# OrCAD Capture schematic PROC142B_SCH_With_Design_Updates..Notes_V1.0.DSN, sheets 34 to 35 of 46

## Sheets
34 34. PRU HEADER: size C; title: SOC LFOSC0 AND SOC BOOTMODE INPUT PINS, PRU HEADER
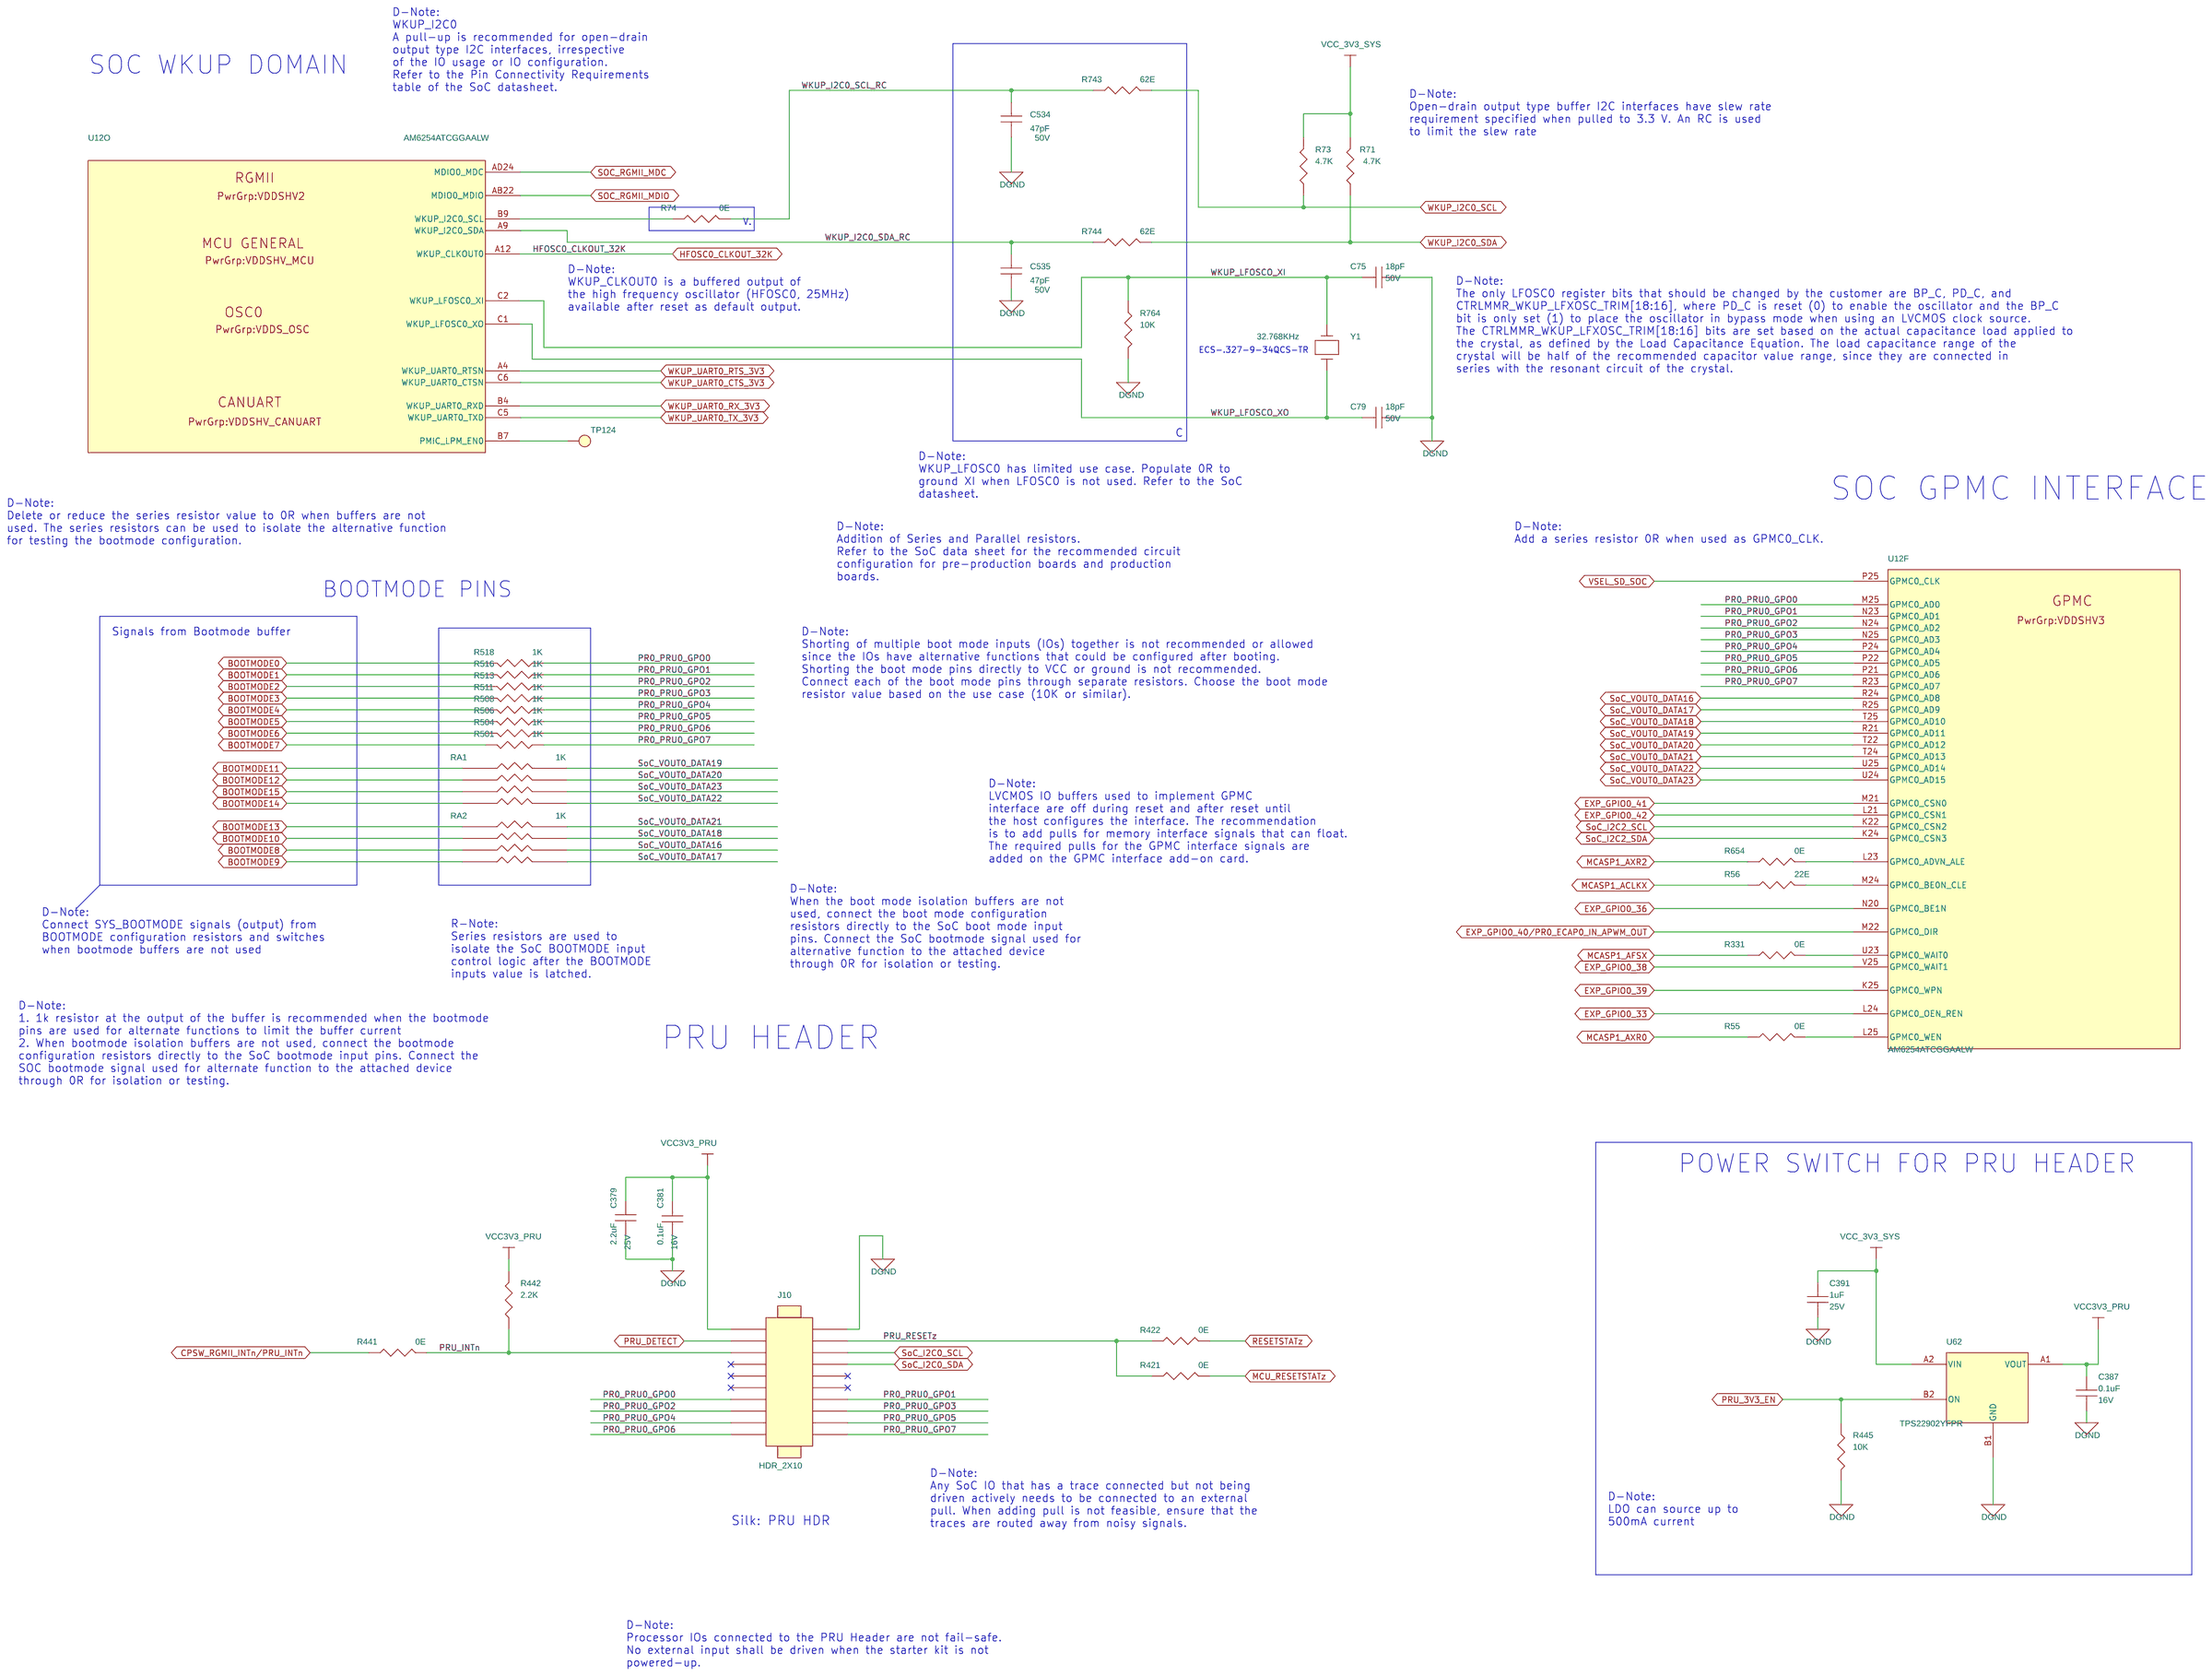
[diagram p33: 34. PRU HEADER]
35 35. USER EXPANSION CONNECTOR: size C; title: USER EXPANSION CONNECTOR
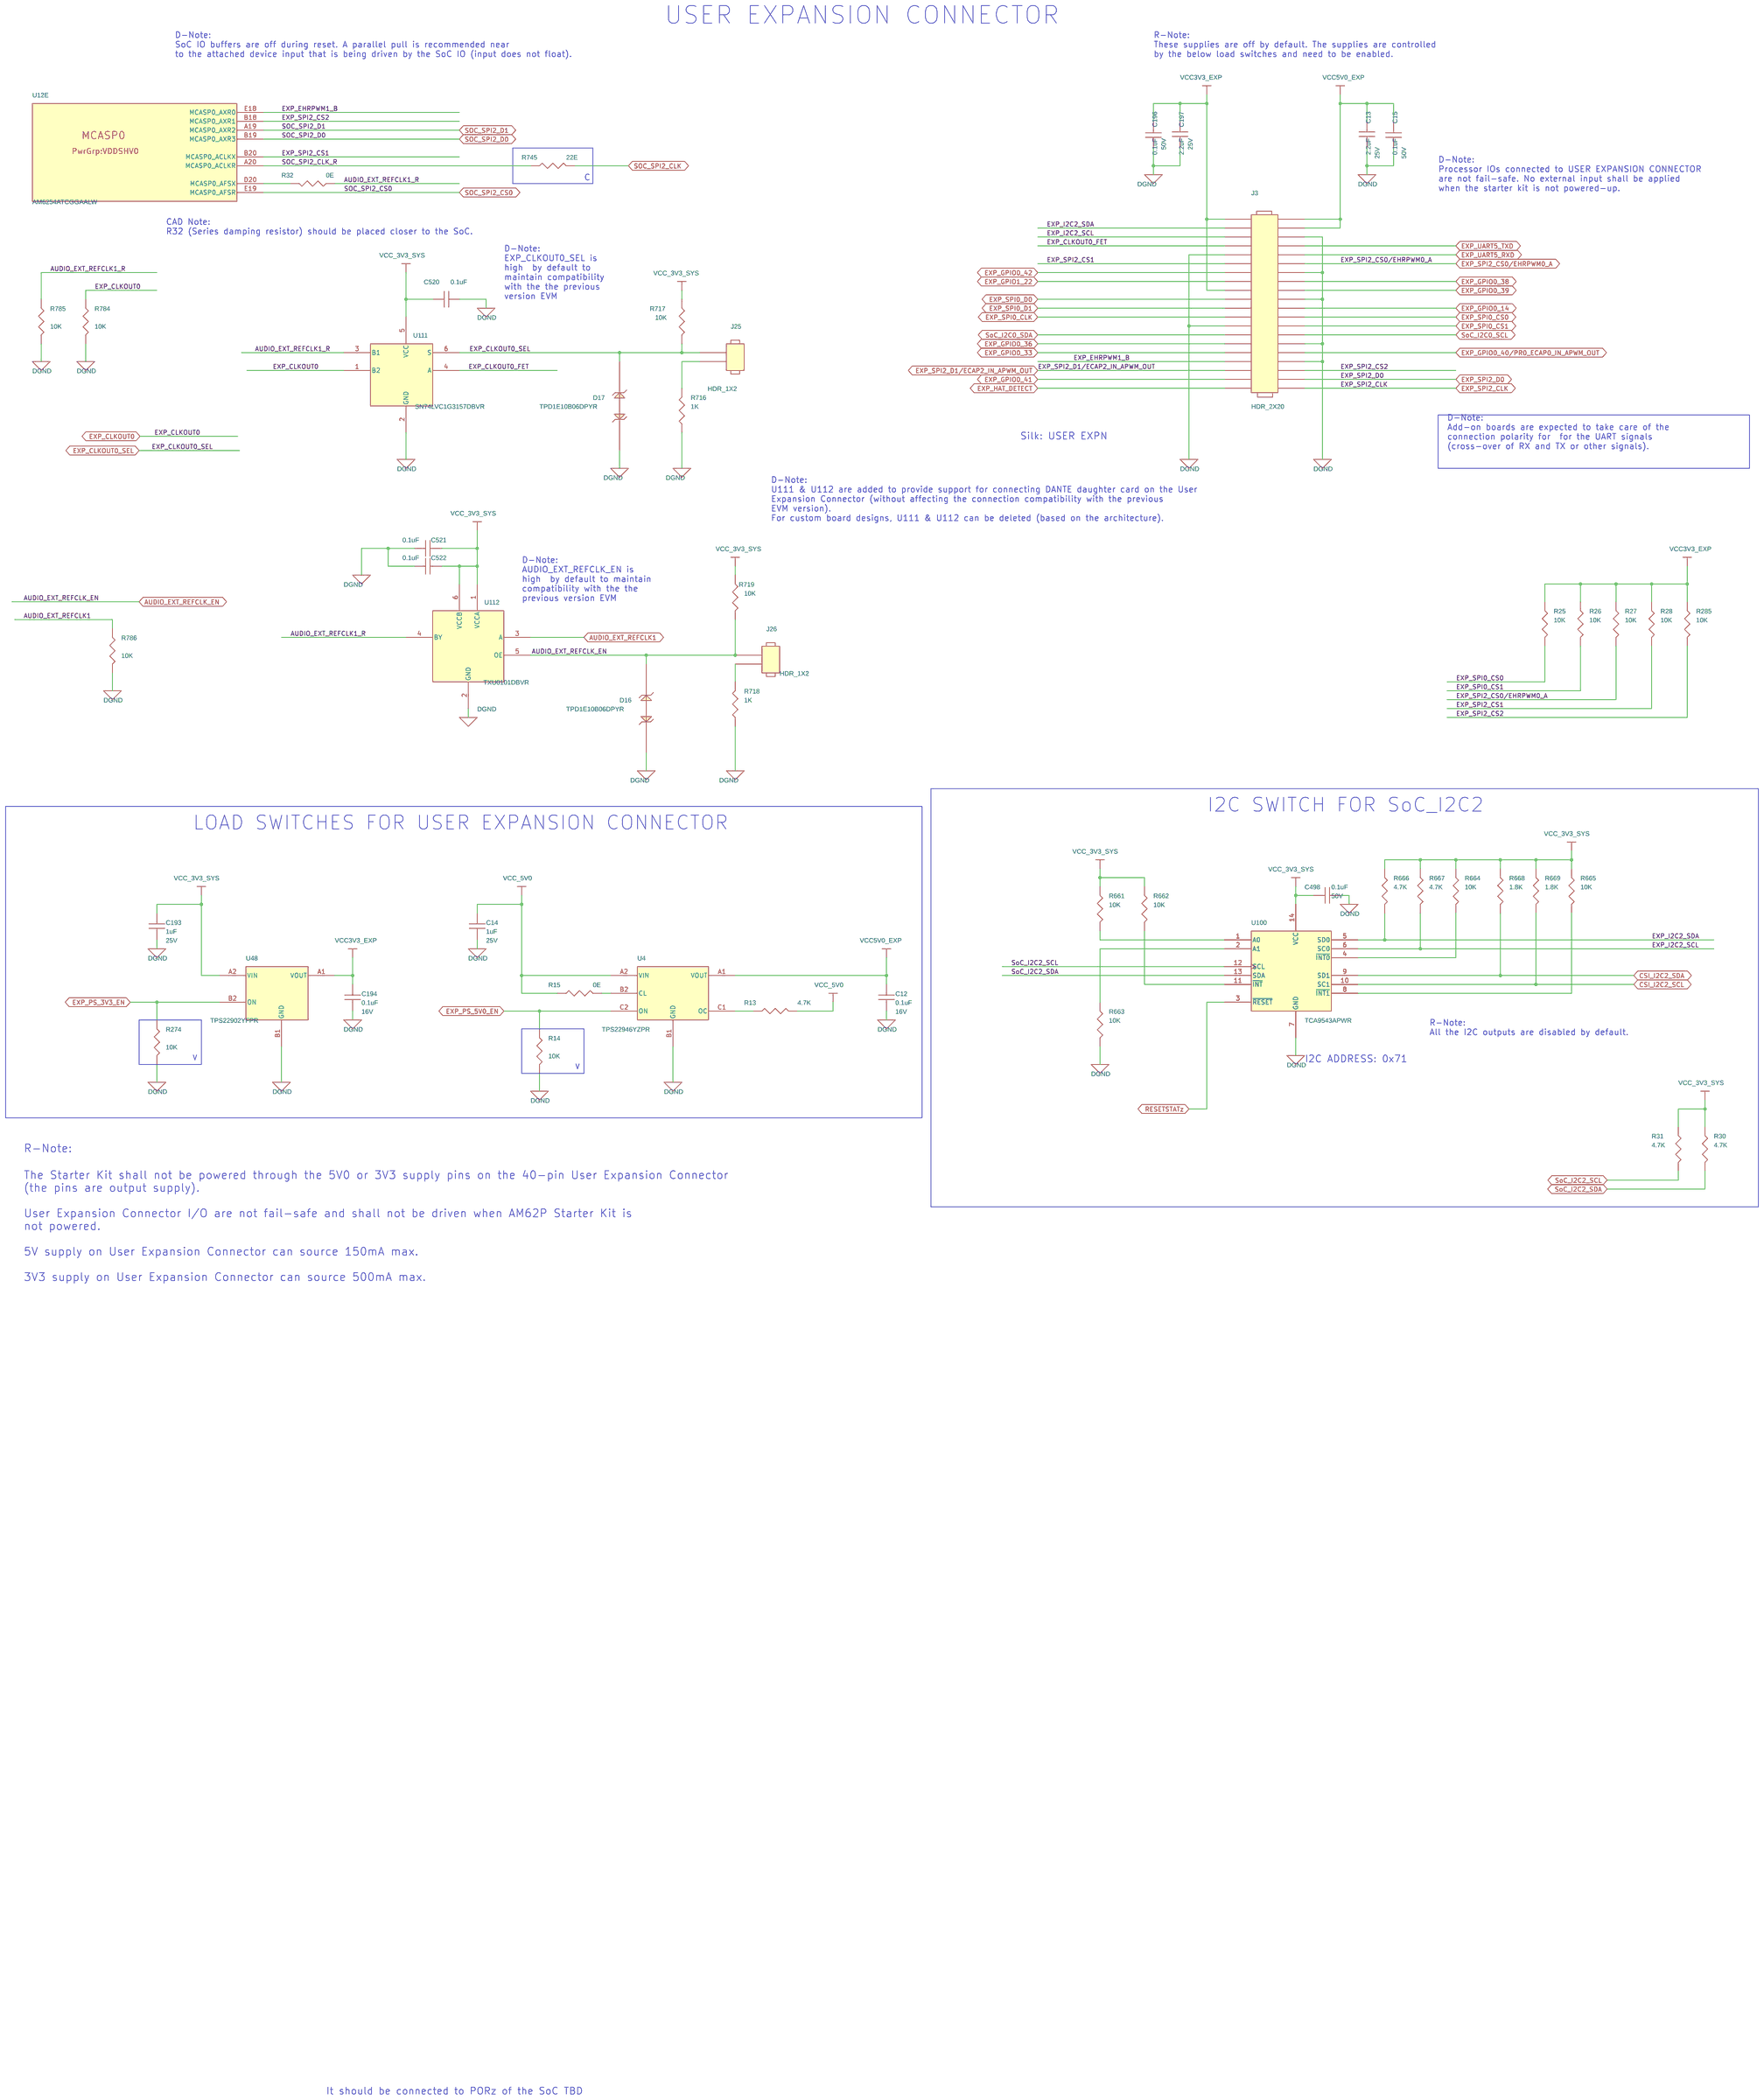
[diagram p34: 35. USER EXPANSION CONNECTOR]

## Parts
sheet 34. PRU HEADER
C75  18pF  [CAP0402_0-75]
C79  18pF  [CAP0402_0-75]
C379  2.2uF  [CAP0402_0-75]
C381  0.1uF  [CAP0201_0-5]
C387  0.1uF  [CAP0201_0-5]
C391  1uF  [CAP0402_0-75]
C534  47pF  [CAP0201_0-5]
C535  47pF  [CAP0201_0-5]
J10  HDR_2X10  [HDR_2X10_PREC010DAAN_S_T_8-4]
R55  0E  [RES0201_0-5]
R56  22E  [RES0402_0-5]
R71  4.7K  [RES0201_0-5]
R73  4.7K  [RES0201_0-5]
R74  0E  [RES0201_0-5]
R331  0E  [RES0201_0-5]
R421  0E  [RES0402_0-5]
R422  0E  [RES0201_0-5]
R441  0E  [RES0201_0-5]
R442  2.2K  [RES0201_0-5]
R445  10K  [RES0402_0-5]
R501  1K  [RES0402_0-5]
R504  1K  [RES0402_0-5]
R506  1K  [RES0402_0-5]
R508  1K  [RES0402_0-5]
R511  1K  [RES0402_0-5]
R513  1K  [RES0402_0-5]
R516  1K  [RES0402_0-5]
R518  1K  [RES0402_0-5]
R654  0E  [RES0201_0-5]
R743  62E  [RES0201_0-5]
R744  62E  [RES0201_0-5]
R764  10K  [RES0402_0-5]
RA1  1K  [RESA_EXB_0201-4_0-5]
RA2  1K  [RESA_EXB_0201-4_0-5]
TP124  TP20_SMD  [TP20_SMD]
U62  TPS22902YFPR  [DSBGA4_15-74_30X30_0-5]
Y1  32.768KHz  [XTAL_ECS-32_130X60_SMD_0-9]
sheet 35. USER EXPANSION CONNECTOR
C12  0.1uF  [CAP0201_0-5]
C13  2.2uF  [CAP0402_0-75]
C14  1uF  [CAP0402_0-75]
C15  0.1uF  [CAP0402_0-75]
C193  1uF  [CAP0402_0-75]
C194  0.1uF  [CAP0201_0-5]
C196  0.1uF  [CAP0402_0-75]
C197  2.2uF  [CAP0402_0-75]
C498  0.1uF  [CAP0402_0-75]
C520  0.1uF  [CAP0402_0-75]
C521  0.1uF  [CAP0201_0-5]
C522  0.1uF  [CAP0201_0-5]
D16  TPD1E10B06DPYR  [DIO_DFN0402_0-5]
D17  TPD1E10B06DPYR  [DIO_DFN0402_0-5]
J3  HDR_2X20  [HDR_2X20_PEC20DAAN_S_T_8-6]
J25  HDR_1X2  [HDR_1X2_90120-0122_S_T_5-6]
J26  HDR_1X2  [HDR_1X2_90120-0122_S_T_5-6]
R13  4.7K  [RES0201_0-5]
R14  10K  [RES0402_0-5]
R15  0E  [RES0201_0-5]
R25  10K  [RES0201_0-5]
R26  10K  [RES0201_0-5]
R27  10K  [RES0201_0-5]
R28  10K  [RES0201_0-5]
R30  4.7K  [RES0201_0-5]
R31  4.7K  [RES0201_0-5]
R32  0E  [RES0201_0-5]
R274  10K  [RES0402_0-5]
R285  10K  [RES0201_0-5]
R661  10K  [RES0201_0-5]
R662  10K  [RES0201_0-5]
R663  10K  [RES0201_0-5]
R664  10K  [RES0201_0-5]
R665  10K  [RES0201_0-5]
R666  4.7K  [RES0201_0-5]
R667  4.7K  [RES0201_0-5]
R668  1.8K  [RES0201_0-5]
R669  1.8K  [RES0201_0-5]
R716  1K  [RES0402_0-5]
R717  10K  [RES0201_0-5]
R718  1K  [RES0402_0-5]
R719  10K  [RES0201_0-5]
R745  22E  [RES0201_0-5]
R784  10K  [RES0402_0-5]
R785  10K  [RES0402_0-5]
R786  10K  [RES0402_0-5]
U4  TPS22946YZPR  [DSBGA6_19-68_40X60_0-5]
U48  TPS22902YFPR  [DSBGA4_15-74_30X30_0-5]
U100  TCA9543APWR  [TSSOP14_25-59_205X180_1-2]
U111  SN74LVC1G3157DBVR  [SOT23-6_1-5]
U112  TXU0101DBVR  [SOT23-6_1-5]
sheet 43. HDMI INTERFACE
U12  AM6254ATCGGAALW  [BGA425_19-68_510X510_0-7]  (sections A,B,C,D,E,F,G,H,I,J,K,L,M,N,O,P,Q,R)

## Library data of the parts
C75 C79 = CAP: CAP CERAMIC 18pF 50V 5% HI-Q C0G(NP0) 0402; Chkd/date: VASANTHA/030315; Crtd /date: NAVEED/271014; Custom_Duty: 15%; Customs_HS_Code: 85322990; Distributor_name: DIGIKEY; Distributor_part_number: 490-3119-1-ND; Footprint Path: Y:\MIS_DATABASE\Library\ALTIUM_TOOL\PCB_FOOTPRINTS\Altium_Footprint_Lib.PcbLib; Height: 0.55MM; Library Path: Y:\MIS_DATABASE\Library\ALTIUM_TOOL\SCHEMATICS_PARTS\MS_DISCRETE_Library.schlib; Mfr_name: MURATA; Mfr_part_number: GJM1555C1H180JB01D; Mistral Part No: 120014100019-R; Package: 0402; Part_type: CAPACITORS\CERAMIC; Project: DC_MIST_RDC; RoHS: RoHS; Temperature: -55°C+125°C; Tolerance: 5%; Voltage: 50V; Wattage: NA; Weight: 6mg; Datasheet: Y:\MIS_DATABASE\DATASHEETS\CAPACITORS\MURATA-GXX-SER_NOV17.PDF
C13 C197 C379 = CAP: CAP CERAMIC 2.2uF 25V 10% X5R 0402; Chkd/date: ALVY/010721; Crtd /date: MANIRAJA/010721; Custom_Duty: 15%; Customs_HS_Code: 85322990; Distributor_name: DIGIKEY; Distributor_part_number: 490-12703-1-ND; Footprint Path: Y:\MIS_DATABASE\Library\ALTIUM_TOOL\PCB_FOOTPRINTS\Altium_Footprint_Lib.PcbLib; Height: 0.70MM; Library Path: Y:\MIS_DATABASE\Library\ALTIUM_TOOL\SCHEMATICS_PARTS\MS_DISCRETE_Library.schlib; Mfr_name: MURATA; Mfr_part_number: GRM155R61E225KE11D; Mistral Part No: 120015120001-R; Package: 0402; Part_type: CAPACITORS\CERAMIC; Project: TI_AM263X_CC; RoHS: RoHS; Temperature: -55°C+85°C; Tolerance: 10%; Voltage: 25V; Wattage: NA; Weight: 1.5mg; Datasheet: Y:\MIS_DATABASE\DATASHEETS\CAPACITORS\GRM155R61E225KE11.PDF
C381 C521 C522 = CAP: CAP CERAMIC 0.1uF 16V 10% X5R 0201; Alt_Mfr_name: YAGEO AMERICA; Alt_Mfr_part_number: CC0402KRX5R8BB104; Chkd/date: MANIRAJA/230118; Crtd /date: MANIRAJA/230118; Custom_Duty: 15%; Customs_HS_Code: 85322990; Distributor_name: DIGIKEY; Distributor_part_number: 490-14305-1-ND; Footprint Path: Y:\MIS_DATABASE\Library\ALTIUM_TOOL\PCB_FOOTPRINTS\Altium_Footprint_Lib.PcbLib; Height: 0.33MM; Library Path: Y:\MIS_DATABASE\Library\ALTIUM_TOOL\SCHEMATICS_PARTS\MS_DISCRETE_Library.schlib; Mfr_name: MURATA; Mfr_part_number: GRM033R61C104KE14D; Mistral Part No: 120009030072-R; Package: 0201; Part_type: CAPACITORS\CERAMIC; Project: TI_MAXIE_CPB; RoHS: RoHS; Temperature: -55°C+85°C; Tolerance: 10%; Voltage: 16V; Wattage: NA; Weight: 0.33mg; Datasheet: Y:\MIS_DATABASE\DATASHEETS\CAPACITORS\GRM033R61C104KE14.PDF
C387 = CAP: CAP CERAMIC 0.1uF 16V 10% X5R 0201; Chkd/date: PRADEEP/130623; Crtd /date: PRADEEP/130623; Custom_Duty: 15%; Customs_HS_Code: 85322990; Distributor_name: NA; Distributor_part_number: NA; Footprint Path: Y:\MIS_DATABASE\Library\ALTIUM_TOOL\PCB_FOOTPRINTS\Altium_Footprint_Lib.PcbLib; Height: 0.33MM; Library Path: Y:\MIS_DATABASE\Library\ALTIUM_TOOL\SCHEMATICS_PARTS\MS_DISCRETE_Library.schlib; Mfr_name: MURATA; Mfr_part_number: GRT033R61C104KE01; Mistral Part No: 120022060019-R; Package: 0201; Part_type: CAPACITORS\CERAMIC; Project: AM62P_SK; RoHS: RoHS; Temperature: -55°C+85°C; Tolerance: 10%; Voltage: 16V; Wattage: NA; Weight: 0.33mg; Datasheet: Y:\MIS_DATABASE\DATASHEETS\CAPACITORS\GRT033R61C104KE01XX.PDF
C14 C193 C391 = CAP: CAP CERAMIC 1uF 25V 10% X6S 0402; Chkd/date: MANIRAJA/140518; Crtd /date: ALVY/140518; Custom_Duty: 15%; Customs_HS_Code: 85322990; Distributor_name: DIGIKEY; Distributor_part_number: 490-10014-1-ND; Footprint Path: Y:\MIS_DATABASE\Library\ALTIUM_TOOL\PCB_FOOTPRINTS\Altium_Footprint_Lib.PcbLib; Height: 0.60MM; Library Path: Y:\MIS_DATABASE\Library\ALTIUM_TOOL\SCHEMATICS_PARTS\MS_DISCRETE_Library.schlib; Mfr_name: MURATA; Mfr_part_number: GRM155C81E105KE11D; Mistral Part No: 120018050004-R; Package: 0402; Part_type: CAPACITORS\CERAMIC; Project: TI_SVB_MAXWELL_DUT; RoHS: RoHS; Temperature: -55°C+105°C; Tolerance: 10%; Voltage: 25V; Wattage: NA; Weight: 6mg; Datasheet: Y:\MIS_DATABASE\DATASHEETS\CAPACITORS\GRM155C81E105KE11X.PDF
C534 C535 = CAP: CAP CERAMIC 47pF 50V 5% C0G(NP0) AUTO 0201; Chkd/date: MANIRAJA/311221; Crtd /date: ALVY/301221; Custom_Duty: 15%; Customs_HS_Code: 85322990; Distributor_name: MOUSER; Distributor_part_number: 81-GRT0335C1H470JA2D; Footprint Path: Y:\MIS_DATABASE\Library\ALTIUM_TOOL\PCB_FOOTPRINTS\Altium_Footprint_Lib.PcbLib; Height: 0.33MM; Library Path: Y:\MIS_DATABASE\Library\ALTIUM_TOOL\SCHEMATICS_PARTS\MS_DISCRETE_Library.schlib; Mfr_name: MURATA; Mfr_part_number: GRT0335C1H470JA02D; Mistral Part No: 120021120018-R; Package: 0201; Part_type: CAPACITORS\CERAMIC; Project: AM62Q_SKEVM_BRD; RoHS: RoHS; Temperature: -55°C+125°C; Tolerance: 5%; Voltage: 50V; Wattage: NA; Weight: 0.33mg; Datasheet: Y:\MIS_DATABASE\DATASHEETS\CAPACITORS\GRT0335C1H470JA02.PDF
J10 = HEADER_10X2: CON HDR 2X10 2.54MM PITCH ST TH; Chkd/date: MANIRAJA/270721; Crtd /date: ALVY/260721; Custom_Duty: 24%; Customs_HS_Code: 85369090; Distributor_name: DIGIKEY; Distributor_part_number: S2012EC-10-ND; Footprint Path: Y:\MIS_DATABASE\Library\ALTIUM_TOOL\PCB_FOOTPRINTS\Altium_Footprint_Lib.PcbLib; Height: 8.34MM; Library Path: Y:\MIS_DATABASE\Library\ALTIUM_TOOL\SCHEMATICS_PARTS\MS_CONNECTOR_Library.schlib; Mfr_name: SULLINS CONNECTOR; Mfr_part_number: PREC010DAAN-RC; Mistral Part No: 150021070022-R; Package: THRU-HOLE; Part_type: CONNECTOR\HEADERS; Project: TI_AM335x SK_BRD; RoHS: RoHS; Temperature: -40°C+105°C; Tolerance: NA; Voltage: NA; Wattage: NA; Weight: NA; Datasheet: Y:\MIS_DATABASE\DATASHEETS\CONNECTORS\PRPCXXDXXN-SER.PDF
R55 R74 R331 R654 = RESISTOR: RES 0E 1/20W 5% 0201; Chkd/date: NAVEED/301214; Crtd /date: MUDDU/120710; Custom_Duty: 15%; Customs_HS_Code: 85332119; Distributor_name: DIGIKEY; Distributor_part_number: 311-0.0NCT-ND; Footprint Path: Y:\MIS_DATABASE\Library\ALTIUM_TOOL\PCB_FOOTPRINTS\Altium_Footprint_Lib.PcbLib; Height: 0.26MM; Library Path: Y:\MIS_DATABASE\Library\ALTIUM_TOOL\SCHEMATICS_PARTS\MS_DISCRETE_Library.schlib; Mfr_name: YAGEO AMERICA; Mfr_part_number: RC0201JR-070RL; Mistral Part No: 110010070067-R; Package: 0201; Part_type: RESISTORS\FIXED; Project: PB_BUGBASE; RoHS: RoHS; SIGNAL_MODEL: RESISTOR_RES0201_0-5_0E_0E; Temperature: -55°C+125°C; Tolerance: 5%; Voltage: NA; Wattage: 1/20W; Weight: 0.17mg; Datasheet: Y:\MIS_DATABASE\DATASHEETS\RESISTORS\RCXXXXL-SER_MAR18.PDF
R56 = RESISTOR: RES 22E 1/16W 5% 0402; Chkd/date: ALVY/210122; Crtd /date: TAMILARASU/210122; Custom_Duty: 15%; Customs_HS_Code: 85332119; Distributor_name: DIGIKEY; Distributor_part_number: 311-22JRCT-ND; Footprint Path: Y:\MIS_DATABASE\Library\ALTIUM_TOOL\PCB_FOOTPRINTS\Altium_Footprint_Lib.PcbLib; Height: 0.40MM; Library Path: Y:\MIS_DATABASE\Library\ALTIUM_TOOL\SCHEMATICS_PARTS\MS_DISCRETE_Library.schlib; Manufacturer: YAGEO; Mfr_name: YAGEO AMERICA; Mfr_part_number: RC0402JR-0722RL; Mistral Part No: 110022010018-R; Package: 0402; Part_type: RESISTORS\FIXED; Project: DLRL DIGITAL RECEIVER_BRD; RoHS: RoHS; Temperature: -55°C+155°C; Tolerance: 5%; Voltage: NA; Wattage: 1/16W; Weight: 0.65mg; Datasheet: Y:\MIS_DATABASE\DATASHEETS\RESISTORS\RCXXXXP-SER_SEP18.PDF
R13 R30 R31 R71 R73 R666 R667 = RESISTOR: RES 4.7K 1/20W 5% 0201; Chkd/date: MANIRAJA/200921; Crtd /date: ALVY/200921; Custom_Duty: 15%; Customs_HS_Code: 85332119; Distributor_name: DIGIKEY; Distributor_part_number: 311-4.7KNCT-ND; Footprint Path: Y:\MIS_DATABASE\Library\ALTIUM_TOOL\PCB_FOOTPRINTS\Altium_Footprint_Lib.PcbLib; Height: 0.26MM; Library Path: Y:\MIS_DATABASE\Library\ALTIUM_TOOL\SCHEMATICS_PARTS\MS_DISCRETE_Library.schlib; Mfr_name: YAGEO AMERICA; Mfr_part_number: RC0201JR-074K7L; Mistral Part No: 110021090007-R; Package: 0201; Part_type: RESISTORS\FIXED; Project: TI_AM62x SKEVM_BRD; RoHS: RoHS; Temperature: -55°C+125°C; Tolerance: 5%; Voltage: NA; Wattage: 1/20W; Weight: 0.17mg; Datasheet: Y:\MIS_DATABASE\DATASHEETS\RESISTORS\RCXXXXL-SER_MAR18.PDF
R421 = RESISTOR: RES 0E 1/16W JUMPER 0402; Chkd/date: VASANTHA/201216; Crtd /date: MUDDU/190810; Custom_Duty: 15%; Customs_HS_Code: 85332119; Distributor_name: DIGIKEY; Distributor_part_number: 541-0.0JCT-ND; Footprint Path: Y:\MIS_DATABASE\Library\ALTIUM_TOOL\PCB_FOOTPRINTS\Altium_Footprint_Lib.PcbLib; Height: 0.40MM; Library Path: Y:\MIS_DATABASE\Library\ALTIUM_TOOL\SCHEMATICS_PARTS\MS_DISCRETE_Library.schlib; Mfr_name: VISHAY; Mfr_part_number: CRCW04020000Z0ED; Mistral Part No: 110010080019-R; Package: 0402; Part_type: RESISTORS\FIXED; Project: PB_BUGBASE; RoHS: RoHS; Temperature: -55°C+155°C; Tolerance: NA; Voltage: NA; Wattage: 1/16W; Weight: 0.65mg; Datasheet: Y:\MIS_DATABASE\DATASHEETS\RESISTORS\CRCW0603.PDF
R15 R32 R422 R441 = RESISTOR: RES 0E 1/20W 5% 0201; Chkd/date: NAVEED/301214; Crtd /date: MUDDU/120710; Custom_Duty: 15%; Customs_HS_Code: 85332119; Distributor_name: DIGIKEY; Distributor_part_number: 311-0.0NCT-ND; Footprint Path: Y:\MIS_DATABASE\Library\ALTIUM_TOOL\PCB_FOOTPRINTS\Altium_Footprint_Lib.PcbLib; Height: 0.26MM; Library Path: Y:\MIS_DATABASE\Library\ALTIUM_TOOL\SCHEMATICS_PARTS\MS_DISCRETE_Library.schlib; Mfr_name: YAGEO AMERICA; Mfr_part_number: RC0201JR-070RL; Mistral Part No: 110010070067-R; Package: 0201; Part_type: RESISTORS\FIXED; Project: PB_BUGBASE; RoHS: RoHS; Temperature: -55°C+125°C; Tolerance: 5%; Voltage: NA; Wattage: 1/20W; Weight: 0.17mg; Datasheet: Y:\MIS_DATABASE\DATASHEETS\RESISTORS\RCXXXXL-SER_MAR18.PDF
R442 = RESISTOR: RES 2.2K 1/20W 5% 0201; Chkd/date: VASANTHA/010117; Crtd /date: MAZHAR/010605; Custom_Duty: 15%; Customs_HS_Code: 85332119; Distributor_name: DIGIKEY; Distributor_part_number: P2.2KAGCT-ND; Footprint Path: Y:\MIS_DATABASE\Library\ALTIUM_TOOL\PCB_FOOTPRINTS\Altium_Footprint_Lib.PcbLib; Height: 0.26MM; Library Path: Y:\MIS_DATABASE\Library\ALTIUM_TOOL\SCHEMATICS_PARTS\MS_DISCRETE_Library.schlib; Mfr_name: PANASONIC-ECG; Mfr_part_number: ERJ-1GEJ222C; Mistral Part No: 110009030427-R; Package: 0201; Part_type: RESISTORS\FIXED; Project: G4SLIM; RoHS: RoHS; Temperature: -55°C+125°C; Tolerance: 5%; Voltage: NA; Wattage: 1/20W; Weight: 0.15mg; Datasheet: Y:\MIS_DATABASE\DATASHEETS\RESISTORS\PAN-ERJXGE-FEB06.PDF
R14 R274 R445 R764 R784-R786 = RESISTOR: RES 10K 1/16W 5% 0402; Chkd/date: MANIRAJA/120219; Crtd /date: MANIRAJA/120219; Custom_Duty: 15%; Customs_HS_Code: 85332119; Distributor_name: DIGIKEY; Distributor_part_number: 541-10KJCT-ND; Footprint Path: Y:\MIS_DATABASE\Library\ALTIUM_TOOL\PCB_FOOTPRINTS\Altium_Footprint_Lib.PcbLib; Height: 0.40MM; Library Path: Y:\MIS_DATABASE\Library\ALTIUM_TOOL\SCHEMATICS_PARTS\MS_DISCRETE_Library.schlib; Mfr_name: VISHAY; Mfr_part_number: CRCW040210K0JNED; Mistral Part No: 110011060021-R; Package: 0402; Part_type: RESISTORS\FIXED; Project: NEXTNAV_ORBIT_MODULE; RoHS: RoHS; Temperature: -55°C+155°C; Tolerance: 5%; Voltage: NA; Wattage: 1/16W; Weight: 0.65mg; Datasheet: Y:\MIS_DATABASE\DATASHEETS\RESISTORS\CRCW0603.PDF
R501 R504 R506 R508 R511 R513 R516 R518 R716 R718 = RESISTOR: RES 1K 1/10W 5% 0402; Chkd/date: VASANTHA/201216; Crtd /date: MAZHAR/230805; Custom_Duty: 15%; Customs_HS_Code: 85332119; Distributor_name: DIGIKEY; Distributor_part_number: P1.0KJCT-ND; Footprint Path: Y:\MIS_DATABASE\Library\ALTIUM_TOOL\PCB_FOOTPRINTS\Altium_Footprint_Lib.PcbLib; Height: 0.40MM; Library Path: Y:\MIS_DATABASE\Library\ALTIUM_TOOL\SCHEMATICS_PARTS\MS_DISCRETE_Library.schlib; Mfr_name: PANASONIC-ECG; Mfr_part_number: ERJ-2GEJ102X; Mistral Part No: 110009030400-R; Package: 0402; Part_type: RESISTORS\FIXED; Project: HSE; RoHS: RoHS; Temperature: -55°C+155°C; Tolerance: 5%; Voltage: NA; Wattage: 1/10W; Weight: 0.8mg; Datasheet: Y:\MIS_DATABASE\DATASHEETS\RESISTORS\PAN-ERJSER_NOV17.PDF
R743 R744 = RESISTOR: RES 62E 1/20W 1% 0201; Chkd/date: PRADEEP/230326; Crtd /date: SHANKARI/230326; Custom_Duty: 15%; Customs_HS_Code: 85332119; Distributor_name: DIGIKEY; Distributor_part_number: P123108CT-ND; Footprint Path: Y:\MIS_DATABASE\Library\ALTIUM_TOOL\PCB_FOOTPRINTS\Altium_Footprint_Lib.PcbLib; Height: 0.26MM; Library Path: Y:\MIS_DATABASE\Library\ALTIUM_TOOL\SCHEMATICS_PARTS\MS_DISCRETE_Library.schlib; Mfr_name: PANASONIC; Mfr_part_number: ERJ-1GNF62R0C; Mistral Part No: 110026030006-R; Package: 0201; Part_type: RESISTORS\FIXED; Project: AM62X_FULTON_REV B; RoHS: RoHS; Temperature: -55°C+125°C; Tolerance: 0.01; Voltage: NA; Wattage: 1/20W; Weight: NA; Datasheet: Y:\MIS_DATABASE\DATASHEETS\RESISTORS\ERJ-1GNF62R0C.PDF
RA1 RA2 = RESARR_ISO4: RES ARRAY 1K 31mW 5% 0201-4; Chkd/date: NAVEED/110515; Crtd /date: VASANTHA/080515; Custom_Duty: 15%; Customs_HS_Code: 85332119; Distributor_name: DIGIKEY; Distributor_part_number: Y6102CT-ND; Footprint Path: Y:\MIS_DATABASE\Library\ALTIUM_TOOL\PCB_FOOTPRINTS\Altium_Footprint_Lib.PcbLib; Height: 0.45MM; Library Path: Y:\MIS_DATABASE\Library\ALTIUM_TOOL\SCHEMATICS_PARTS\MS_DISCRETE_Library.schlib; Manufacturer: PANASONIC-ECG; Mfr_part_number: EXB-18V102JX; Mistral Part No: 110015050003-R; Package: 0201-4; Part_type: RESISTORS\ARRAY; Project: FREE SCALE NANO; RoHS: RoHS; Temperature: -55°C+125°C; Tolerance: 5%; Voltage: NA; Wattage: 31mW; Weight: 1mg; Datasheet: Y:\MIS_DATABASE\DATASHEETS\RESISTORS\EXB-18V.PDF
TP124 = TESTPOINT: TESTPOINT CIR 20 SMD; Chkd/date: SHREESHAIL/171006; Crtd /date: MAZHAR/171006; Custom_Duty: NA; Customs_HS_Code: NA; Distributor_name: NA; Distributor_part_number: NA; Footprint Path: Y:\MIS_DATABASE\Library\ALTIUM_TOOL\PCB_FOOTPRINTS\Altium_Footprint_Lib.PcbLib; Height: NA; Library Path: Y:\MIS_DATABASE\Library\ALTIUM_TOOL\SCHEMATICS_PARTS\MS_DISCRETE_Library.schlib; MECHANICAL 3D STEP FILE: NA; Mfr_name: LOCAL; Mistral Part No: NA; Package: SMD; Project: BT MODULE_CSRBC04; RoHS: NA; Temperature: NA; Tolerance: NA; Voltage: NA; Wattage: NA; Weight: NA; Datasheet: NA
U48 U62 = TPS22912CYZVR_DSBGA4: IC 3.6V 500mA 78mE ON-RESISTANCE LOAD SWITCH WITH CONTROLLED TURNON DSBGA4; Chkd/date: MANIRAJA/170920; Crtd /date: ALVY/160920; Custom_Duty: 15%; Customs_HS_Code: 85423100; Distributor_name: DIGIKEY; Distributor_part_number: 296-24472-1-ND; Footprint Path: Y:\MIS_DATABASE\Library\ALTIUM_TOOL\PCB_FOOTPRINTS\Altium_Footprint_Lib.PcbLib; Height: 0.50MM; Library Path: Y:\MIS_DATABASE\Library\ALTIUM_TOOL\SCHEMATICS_PARTS\MS_MISCPOWER_Library.schlib; Mfr_name: TEXAS INSTRUMENTS; Mistral Part No: 142020090007-R; Package: DSBGA4; Part_type: ICS\POWER; Project: AM64X_SKEVM; RoHS: RoHS; Temperature: -40°C+85°C; Tolerance: NA; Voltage: NA; Wattage: NA; Weight: 0.7mg; Datasheet: Y:\MIS_DATABASE\DATASHEETS\ICS\POWER\TPS22901-2-3.PDF
Y1 = CRY: CRY 32.768KHz 9pF SMD; Chkd/date: VASANTHA/090419; Crtd /date: ALVY/090419; Custom_Duty: 24%; Customs_HS_Code: 85439000; Distributor_name: DIGIKEY; Distributor_part_number: XC2160CT-ND; Footprint Path: Y:\MIS_DATABASE\Library\ALTIUM_TOOL\PCB_FOOTPRINTS\Altium_Footprint_Lib.PcbLib; Height: 0.90MM; Library Path: Y:\MIS_DATABASE\Library\ALTIUM_TOOL\SCHEMATICS_PARTS\MS_DISCRETE_Library.schlib; Mfr_name: ECS INC; Mfr_part_number: ECS-.327-9-34QCS-TR; Mistral Part No: 130019040003-R; Package: SMD; Part_type: CRYSTAL; Project: J7ES_SOM_DUAL-LEO_PMIC; RoHS: RoHS; Temperature: -40°C+125°C; Tolerance: NA; Voltage: NA; Wattage: NA; Weight: 16mg; Datasheet: Y:\MIS_DATABASE\DATASHEETS\MISC\CRY_OSC\ECS-34Q.PDF
C12 C194 = CAP: CAP CERAMIC 0.1uF 16V 10% X5R 0201; Chkd/date: MANIRAJA/230118; Crtd /date: MANIRAJA/230118; Custom_Duty: 15%; Customs_HS_Code: 85322990; Distributor_name: DIGIKEY; Distributor_part_number: 490-14305-1-ND; Footprint Path: Y:\MIS_DATABASE\Library\ALTIUM_TOOL\PCB_FOOTPRINTS\Altium_Footprint_Lib.PcbLib; Height: 0.33MM; Library Path: Y:\MIS_DATABASE\Library\ALTIUM_TOOL\SCHEMATICS_PARTS\MS_DISCRETE_Library.schlib; Mfr_name: MURATA; Mfr_part_number: GRM033R61C104KE14D; Mistral Part No: 120009030072-R; Package: 0201; Part_type: CAPACITORS\CERAMIC; Project: TI_MAXIE_CPB; RoHS: RoHS; Temperature: -55°C+85°C; Tolerance: 10%; Voltage: 16V; Wattage: NA; Weight: 0.33mg; Datasheet: Y:\MIS_DATABASE\DATASHEETS\CAPACITORS\GRM033R61C104KE14.PDF
C15 C196 C498 C520 = CAP: CAP CERAMIC 0.1uF 50V 10% X7R 0402; Alt_Mfr_name: YAGEO AMERICA; Alt_Mfr_part_number: CC0402KRX5R8BB104; Chkd/date: MANIRAJA/261020; Crtd /date: ALVY/211020; Custom_Duty: 15%; Customs_HS_Code: 85322990; Distributor_name: DIGIKEY; Distributor_part_number: 490-10700-1-ND; Footprint Path: Y:\MIS_DATABASE\Library\ALTIUM_TOOL\PCB_FOOTPRINTS\Altium_Footprint_Lib.PcbLib; Height: 0.55MM; Library Path: Y:\MIS_DATABASE\Library\ALTIUM_TOOL\SCHEMATICS_PARTS\MS_DISCRETE_Library.schlib; Mfr_name: MURATA; Mfr_part_number: GRM155R71H104KE14D; Mistral Part No: 120011100014-R; Package: 0402; Part_type: CAPACITORS\CERAMIC; Project: J7_CP; RoHS: RoHS; Temperature: -55°C+125°C; Tolerance: 10%; Voltage: 50V; Wattage: NA; Weight: 3.1mg; Datasheet: Y:\MIS_DATABASE\DATASHEETS\CAPACITORS\GRM155R71H104KE14.PDF
D16 D17 = DIODE_SOD323: DIODE 1CH ESD PROTECTION X1SON2; Chkd/date: MANIRAJA/040420; Crtd /date: VASANTHA/181114; Custom_Duty: 15%; Customs_HS_Code: 85423100; Distributor_name: DIGIKEY; Distributor_part_number: 296-30406-1-ND; Footprint Path: Y:\MIS_DATABASE\Library\ALTIUM_TOOL\PCB_FOOTPRINTS\Altium_Footprint_Lib.PcbLib; Height: 0.45MM; Library Path: Y:\MIS_DATABASE\Library\ALTIUM_TOOL\SCHEMATICS_PARTS\MS_DISCRETE_Library.schlib; Mfr_name: TEXAS INSTRUMENTS; Mistral Part No: 130014110022-R; Package: X1SON2; Part_type: DIODE; Project: GALILEO_EVM; RoHS: RoHS; Temperature: -40°C+125°C; Tolerance: NA; Voltage: NA; Wattage: NA; Weight: 1mg; Datasheet: Y:\MIS_DATABASE\DATASHEETS\ICS\INTERFACE\TPD1E10B06-SER.PDF
J3 = HEADER_20X2: CON HDR 2X20 2.54MM PITCH ST TH; Chkd/date: MANIRAJA/261020; Crtd /date: MANIRAJA/261020; Custom_Duty: 24%; Customs_HS_Code: 85369090; Distributor_name: DIGIKEY; Distributor_part_number: S2012E-20-ND; Footprint Path: Y:\MIS_DATABASE\Library\ALTIUM_TOOL\PCB_FOOTPRINTS\Altium_Footprint_Lib.PcbLib; Height: 8.58MM; Library Path: Y:\MIS_DATABASE\Library\ALTIUM_TOOL\SCHEMATICS_PARTS\MS_CONNECTOR_Library.schlib; Mfr_name: SULLINS CONNECTOR; Mfr_part_number: PEC20DAAN; Mistral Part No: 150020100013-R; Package: THRU-HOLE; Part_type: CONNECTOR\HEADERS; Project: AM64X_SKEVM; RoHS: RoHS; Temperature: -65°C+125°C; Tolerance: NA; Voltage: NA; Wattage: NA; Weight: NA; Datasheet: Y:\MIS_DATABASE\DATASHEETS\CONNECTORS\XXCXXDXXN.PDF
J25 J26 = HEADER_2X1: CON HDR 1X2 2.54MM PITCH ST TH; Chkd/date: NAVEED/210714; Crtd /date: USMAN/031012; Custom_Duty: 24%; Customs_HS_Code: 85369090; Distributor_name: DIGIKEY; Distributor_part_number: WM8072-ND; Footprint Path: Y:\MIS_DATABASE\Library\ALTIUM_TOOL\PCB_FOOTPRINTS\Altium_Footprint_Lib.PcbLib; Height: 5.60MM; Library Path: Y:\MIS_DATABASE\Library\ALTIUM_TOOL\SCHEMATICS_PARTS\MS_CONNECTOR_Library.schlib; Mfr_name: MOLEX; Mfr_part_number: 90120-0122; Mistral Part No: 150012100005-R; Package: THRU-HOLE; Part_type: CONNECTOR\HEADERS; Project: NPOL_FEP; RoHS: RoHS; Temperature: -55°C+125°C; Tolerance: NA; Voltage: NA; Wattage: NA; Weight: 122mg; Datasheet: Y:\MIS_DATABASE\DATASHEETS\CONNECTORS\90120-XX.PDF
R25-R28 R285 R661-R665 R717 R719 = RESISTOR: RES 10K 1/20W 5% 0201; Chkd/date: MANIRAJA/050517; Crtd /date: MANIRAJA/050517; Custom_Duty: 15%; Customs_HS_Code: 85332119; Distributor_name: DIGIKEY; Distributor_part_number: 311-10KNCT-ND; Footprint Path: Y:\MIS_DATABASE\Library\ALTIUM_TOOL\PCB_FOOTPRINTS\Altium_Footprint_Lib.PcbLib; Height: 0.26MM; Library Path: Y:\MIS_DATABASE\Library\ALTIUM_TOOL\SCHEMATICS_PARTS\MS_DISCRETE_Library.schlib; Mfr_name: YAGEO AMERICA; Mfr_part_number: RC0201JR-0710KL; Mistral Part No: 110010070051-R; Package: 0201; Part_type: RESISTORS\FIXED; Project: GOLDEN-I LITE; RoHS: RoHS; Temperature: -55°C+125°C; Tolerance: 5%; Voltage: NA; Wattage: 1/20W; Weight: 0.17mg; Datasheet: Y:\MIS_DATABASE\DATASHEETS\RESISTORS\RCXXXXL-SER_MAR18.PDF
R668 R669 = RESISTOR: RES 1.8K 1/20W 1% 0201; Chkd/date: SHREESHAIL/091205; Crtd /date: MAZHAR/211005; Custom_Duty: 15%; Customs_HS_Code: 85332119; Distributor_name: DIGIKEY; Distributor_part_number: P1.8KABCT-ND; Footprint Path: Y:\MIS_DATABASE\Library\ALTIUM_TOOL\PCB_FOOTPRINTS\Altium_Footprint_Lib.PcbLib; Height: 0.26MM; Library Path: Y:\MIS_DATABASE\Library\ALTIUM_TOOL\SCHEMATICS_PARTS\MS_DISCRETE_Library.schlib; Manufacturer: PANASONIC-ECG; Mfr_name: YAGEO AMERICA; Mfr_part_number: ERJ-1GEF182C; Mistral Part No: 110009030149-R; Package: 0201; Part_type: RESISTORS\FIXED; Project: G4SLIM; RoHS: RoHS; Temperature: -55°C+125°C; Tolerance: 1%; Voltage: NA; Wattage: 1/20W; Weight: 0.15mg; Datasheet: Y:\MIS_DATABASE\DATASHEETS\RESISTORS\PAN-ERJSER_NOV17.PDF
R745 = RESISTOR: RES 22E 1/20W 5% 0201; Chkd/date: PRADEEP/220424; Crtd /date: SHANKARI/220424; Custom_Duty: 15%; Customs_HS_Code: 85332119; Distributor_name: DIGIKEY; Distributor_part_number: 311-22NCT-ND; Footprint Path: Y:\MIS_DATABASE\Library\ALTIUM_TOOL\PCB_FOOTPRINTS\Altium_Footprint_Lib.PcbLib; Height: 0.26MM; Library Path: Y:\MIS_DATABASE\Library\ALTIUM_TOOL\SCHEMATICS_PARTS\MS_DISCRETE_Library.schlib; Manufacturer: YAGEO; Mfr_name: YAGEO; Mfr_part_number: RC0201JR-0722RL; Mistral Part No: 110024040012-R; Package: 0201; Part_type: RESISTORS\FIXED; Project: J7AEN_SKEVM; RoHS: RoHS; Temperature: -55°C+125°C; Tolerance: 5%; Voltage: NA; Wattage: 1/20W; Weight: NA; Datasheet: Y:\MIS_DATABASE\DATASHEETS\RESISTORS\RC0201JR-0722RL.PDF
U4 = TPS22946_DSBGA6: IC CURRENT-LIMITED LOAD SWITCH WITH SHUTOFF AUTO-RESTART AND OVERCURRENT CONDITION TIME-OUT DSBGA6; Chkd/date: MANIRAJA/220121; Crtd /date: ALVY/220121; Custom_Duty: 15%; Customs_HS_Code: 85423100; Distributor_name: DIGIKEY; Distributor_part_number: 296-25219-1-ND; Footprint Path: Y:\MIS_DATABASE\Library\ALTIUM_TOOL\PCB_FOOTPRINTS\Altium_Footprint_Lib.PcbLib; Height: 0.50MM; Library Path: Y:\MIS_DATABASE\Library\ALTIUM_TOOL\SCHEMATICS_PARTS\MS_MISCPOWER_Library.schlib; Mfr_name: TEXAS INSTRUMENTS; Mistral Part No: 142021010016-R; Package: DSBGA6; Part_type: ICS\POWER\MANAGEMENT; Project: AM64X_SKEVM; RoHS: RoHS; Temperature: -40°C+85°C; Tolerance: NA; Voltage: NA; Wattage: NA; Weight: 1.7mg; Datasheet: Y:\MIS_DATABASE\DATASHEETS\ICS\POWER\TPS22946.PDF
U100 = TCA9543APWR_TSSOP14: IC 2-CHANNEL I2C BUS SWITCH WITH INTERRUPT LOGIC AND RESET TSSOP14; Chkd/date: VASANTHA/060516; Crtd /date: VASANTHA/070316; Custom_Duty: 15%; Customs_HS_Code: 85423100; Distributor_name: DIGIKEY; Distributor_part_number: 296-42157-1-ND; Footprint Path: Y:\MIS_DATABASE\Library\ALTIUM_TOOL\PCB_FOOTPRINTS\Altium_Footprint_Lib.PcbLib; Height: 1.20MM; Library Path: Y:\MIS_DATABASE\Library\ALTIUM_TOOL\SCHEMATICS_PARTS\MS_BUSDRIVERTRANSCEIVER_Library.schlib; Manufacturer: TEXAS INSTRUMENTS; Mistral Part No: 141016030006-R; Package: TSSOP14; Part_type: ICS\DIGITAL\BUSTRANSCEIVER; Project: OCTASIC_3600; RoHS: RoHS; Temperature: -40°C+85°C; Tolerance: NA; Voltage: NA; Wattage: NA; Weight: NA; Datasheet: Y:\MIS_DATABASE\DATASHEETS\ICS\DIGITAL\BUSTRANSCEIVER\TCA9543A.PDF
U111 = SN74LVC1G3157_SOT563-6: IC SPDT ANALOG SWITCH SOT23-6; Chkd/date: PRAVEEN/151122; Crtd /date: TAMILARASU/151122; Custom_Duty: 15%; Customs_HS_Code: 85423100; Distributor_name: DIGIKEY; Distributor_part_number: 296-14908-1-ND; Footprint Path: Y:\MIS_DATABASE\Library\ALTIUM_TOOL\PCB_FOOTPRINTS\Altium_Footprint_Lib.PcbLib; Height: 1.45MM; Library Path: Y:\MIS_DATABASE\Library\ALTIUM_TOOL\SCHEMATICS_PARTS\MS_ANALOG-APPLICATION_Library.schlib; Mfr_name: TEXAS INSTRUMENTS; Mistral Part No: 140122110004-R; Package: SOT23-6; Part_type: ICS\ANALOG\SWITCH; Project: EMCR; RoHS: RoHS; Temperature: -40°C+125°C; Tolerance: NA; Voltage: NA; Wattage: NA; Weight: NA; Datasheet: Y:\MIS_DATABASE\DATASHEETS\ICS\ANALOG\SN74LVC1G3157.PDF
U112 = TXU0101DBVR_SOT23-6: IC DUAL-BIT FIXED DIRECTION VOLTAGE-LEVEL TRANSLATOR WITH SCHMITT-TRIGGER INPUTS AND 3-STATE OUTPUTS SOT23-6; Chkd/date: PRADEEP/050624; Crtd /date: PRADEEP/050624; Custom_Duty: 0.15; Customs_HS_Code: 85423100; Distributor_name: DIGIKEY; Distributor_part_number: 296-TXU0101DBVRCT-ND; Height: 1.45MM; Mfr_name: TEXAS INSTRUMENTS; Mistral Part No: 140124060002-R; Package: SOT23-6; Part_type: ICS\INTERFACE\LEVEL TRANSLATOR; Project: CASDIC_ECU; RoHS: RoHS; Temperature: -40°C+125°C; Tolerance: NA; Voltage: NA; Wattage: NA; Weight: NA; Datasheet: Y:\MIS_DATABASE\DATASHEETS\ICS\INTERFACE\TXU0101D.PDF
U12 = AM62-EVM_BGA425: IC AM62 SoC MICROPROCESSOR BGA425; Chkd/date: ALVY/110621; Crtd /date: MANIRAJA/110621; Custom_Duty: 15%; Customs_HS_Code: 85423100; Distributor_name: NA; Distributor_part_number: NA; Footprint Path: Y:\MIS_DATABASE\Library\ALTIUM_TOOL\PCB_FOOTPRINTS\Altium_Footprint_Lib.PcbLib; Height: 0.65MM; Library Path: Y:\MIS_DATABASE\Library\ALTIUM_TOOL\SCHEMATICS_PARTS\MS_MICROPROCESSOR_Library.schlib; Mfr_name: TEXAS INSTRUMENTS; Mistral Part No: 141221060001; Package: BGA425; Part_type: ICS\DIGITAL\MICROPROCESSOR; Project: AM62_EVM_BRD; RoHS: NA; Temperature: NA; Tolerance: NA; Voltage: NA; Wattage: NA; Weight: NA; Datasheet: Y:\MIS_DATABASE\DATASHEETS\ICS\DIGITAL\MICROCONTROLLER\AM62-SoC_SVB.PDF

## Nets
DGND: C12.2 C13.2 C14.2 C15.1 C75.2 C79.2 C193.2 C194.2 C196.1 C197.2 C379.2 C381.1 C387.2 C391.2 C498.1 C520.1 C521.1 C522.1 C534.2 C535.2 D16.2 D17.2 J3.6 J3.9 J3.14 J3.20 J3.25 J3.30 J3.34 J10.2 R14.2 R274.2 R445.2 R663.2 R716.1 R718.1 R764.2 R784.2 R785.2 R786.2 U4.B1(GND) U48.B1(GND) U62.B1(GND) U100.7(GND) U111.2(GND) U112.2(GND) ; also on sheet 1 3 12 13 14 15 16 17 18 19 20 21 22 23 24 25 26 27 28 29 30 31 32 33 36 37 38 39 40 41 42 43 44 45
VCC3V3_EXP: C194.1 C196.2 C197.1 J3.1 J3.17 R25.1 R26.1 R27.1 R28.1 R285.1 U48.A1(VOUT)
VCC3V3_PRU: C379.1 C381.2 C387.1 J10.1 R442.1 U62.A1(VOUT)
VCC5V0_EXP: C12.1 C13.1 C15.2 J3.2 J3.4 U4.A1(VOUT)
VCC_3V3_SYS: C193.1 C391.1 C498.2 C520.2 C521.2 C522.2 R30.1 R31.1 R71.1 R73.1 R661.1 R662.1 R664.1 R665.1 R666.1 R667.1 R668.1 R669.1 R717.2 R719.2 U48.A2(VIN) U62.A2(VIN) U100.14(VCC) U111.5(VCC) U112.1(VCCA) U112.6(VCCB) ; also on sheet 3 12 14 15 16 20 21 22 24 25 26 27 28 29 31 32 33 36 37 38 39 40 41 42 43 44 45
VCC_5V0: C14.1 R13.2 R15.1 U4.A2(VIN) ; also on sheet 12 13 17 38 43
AUDIO_EXT_REFCLK1: R786.1 U112.3(A) ; also on sheet 43
AUDIO_EXT_REFCLK1_R: R32.1 R785.1 U111.3(B1) U112.4(BY)
AUDIO_EXT_REFCLK_EN: D16.1 J26.1 R719.1 U112.5(OE) ; also on sheet 41
BOOTMODE0: R518.2 ; also on sheet 29
BOOTMODE1: R516.2 ; also on sheet 29
BOOTMODE2: R513.2 ; also on sheet 29
BOOTMODE3: R511.2 ; also on sheet 29
BOOTMODE4: R508.2 ; also on sheet 29
BOOTMODE5: R506.2 ; also on sheet 29
BOOTMODE6: R504.2 ; also on sheet 29
BOOTMODE7: R501.2 ; also on sheet 29
BOOTMODE8: RA2.3 ; also on sheet 29
BOOTMODE9: RA2.4 ; also on sheet 29
BOOTMODE10: RA2.2 ; also on sheet 29
BOOTMODE11: RA1.1 ; also on sheet 29
BOOTMODE12: RA1.2 ; also on sheet 29
BOOTMODE13: RA2.1 ; also on sheet 29
BOOTMODE14: RA1.4 ; also on sheet 29
BOOTMODE15: RA1.3 ; also on sheet 29
CPSW_RGMII_INTn/PRU_INTn: R441.1 ; also on sheet 25 44
CSI_I2C2_SCL: R669.2 U100.10(SC1) ; also on sheet 40
CSI_I2C2_SDA: R668.2 U100.9(SD1) ; also on sheet 40
EXP_CLKOUT0: R784.1 U111.1(B2) ; also on sheet 44
EXP_CLKOUT0_FET: J3.7 U111.4(A)
EXP_CLKOUT0_SEL: D17.1 J25.1 R717.1 U111.6(S) ; also on sheet 41
EXP_EHRPWM1_B: J3.33 U12.E18(MCASP0_AXR0)
EXP_GPIO0_14: J3.22 ; also on sheet 36
EXP_GPIO0_33: J3.31 U12.L24(GPMC0_OEN_REN)
EXP_GPIO0_36: J3.29 U12.N20(GPMC0_BE1N)
EXP_GPIO0_38: J3.16 U12.V25(GPMC0_WAIT1)
EXP_GPIO0_39: J3.18 U12.K25(GPMC0_WPN)
EXP_GPIO0_40/PR0_ECAP0_IN_APWM_OUT: J3.32 U12.M22(GPMC0_DIR)
EXP_GPIO0_41: J3.37 U12.M21(GPMC0_CSN0)
EXP_GPIO0_42: J3.13 U12.L21(GPMC0_CSN1)
EXP_GPIO1_22: J3.15 ; also on sheet 44
EXP_HAT_DETECT: J3.39 ; also on sheet 41
EXP_I2C2_SCL: J3.5 R667.2 U100.6(SC0)
EXP_I2C2_SDA: J3.3 R666.2 U100.5(SD0)
EXP_PS_3V3_EN: R274.1 U48.B2(ON) ; also on sheet 41
EXP_PS_5V0_EN: R14.1 U4.C2(ON) ; also on sheet 41
EXP_SPI0_CLK: J3.23 ; also on sheet 44
EXP_SPI0_CS0: J3.24 R25.2 ; also on sheet 44
EXP_SPI0_CS1: J3.26 R26.2 ; also on sheet 44
EXP_SPI0_D0: J3.19 ; also on sheet 44
EXP_SPI0_D1: J3.21 ; also on sheet 44
EXP_SPI2_CLK: J3.40 ; also on sheet 39
EXP_SPI2_CS0/EHRPWM0_A: J3.12 R27.2 ; also on sheet 39
EXP_SPI2_CS1: J3.11 R28.2 U12.B20(MCASP0_ACLKX)
EXP_SPI2_CS2: J3.36 R285.2 U12.B18(MCASP0_AXR1)
EXP_SPI2_D0: J3.38 ; also on sheet 39
EXP_SPI2_D1/ECAP2_IN_APWM_OUT: J3.35 ; also on sheet 39
EXP_UART5_RXD: J3.10 ; also on sheet 44
EXP_UART5_TXD: J3.8 ; also on sheet 44
HFOSC0_CLKOUT_32K: U12.A12(WKUP_CLKOUT0) ; also on sheet 20
MCASP1_ACLKX: R56.1 ; also on sheet 41
MCASP1_AFSX: R331.1 ; also on sheet 41
MCASP1_AXR0: R55.1 ; also on sheet 41
MCASP1_AXR2: R654.1 ; also on sheet 41
MCU_RESETSTATz: R421.1 ; also on sheet 36 44
PR0_PRU0_GPO0: J10.13 R518.1 U12.M25(GPMC0_AD0)
PR0_PRU0_GPO1: J10.14 R516.1 U12.N23(GPMC0_AD1)
PR0_PRU0_GPO2: J10.15 R513.1 U12.N24(GPMC0_AD2)
PR0_PRU0_GPO3: J10.16 R511.1 U12.N25(GPMC0_AD3)
PR0_PRU0_GPO4: J10.17 R508.1 U12.P24(GPMC0_AD4)
PR0_PRU0_GPO5: J10.18 R506.1 U12.P22(GPMC0_AD5)
PR0_PRU0_GPO6: J10.19 R504.1 U12.P21(GPMC0_AD6)
PR0_PRU0_GPO7: J10.20 R501.1 U12.R23(GPMC0_AD7)
PRU_3V3_EN: R445.1 U62.B2(ON) ; also on sheet 41
PRU_DETECT: J10.3 ; also on sheet 41
PRU_INTn: J10.5 R441.2 R442.2
PRU_RESETz: J10.4 R421.2 R422.2
RESETSTATz: R422.1 U100.3(~{RESET}) ; also on sheet 15 21 22 23 25 26 29 39 41 42 43 44
SoC_I2C0_SCL: J3.28 J10.6 ; also on sheet 12 15 24 39 44
SoC_I2C0_SDA: J3.27 J10.8 ; also on sheet 12 15 24 39 44
SoC_I2C2_SCL: R31.2 U12.K22(GPMC0_CSN2) U100.12(SCL)
SoC_I2C2_SDA: R30.2 U12.K24(GPMC0_CSN3) U100.13(SDA)
SOC_RGMII_MDC: U12.AD24(MDIO0_MDC) ; also on sheet 25 26
SOC_RGMII_MDIO: U12.AB22(MDIO0_MDIO) ; also on sheet 25 26
SOC_SPI2_CLK: R745.2 ; also on sheet 39
SOC_SPI2_CLK_R: R745.1 U12.A20(MCASP0_ACLKR)
SOC_SPI2_CS0: U12.E19(MCASP0_AFSR) ; also on sheet 39
SOC_SPI2_D0: U12.B19(MCASP0_AXR3) ; also on sheet 39
SOC_SPI2_D1: U12.A19(MCASP0_AXR2) ; also on sheet 39
SoC_VOUT0_DATA16: RA2.6 U12.R24(GPMC0_AD8) ; also on sheet 43
SoC_VOUT0_DATA17: RA2.5 U12.R25(GPMC0_AD9) ; also on sheet 43
SoC_VOUT0_DATA18: RA2.7 U12.T25(GPMC0_AD10) ; also on sheet 43
SoC_VOUT0_DATA19: RA1.8 U12.R21(GPMC0_AD11) ; also on sheet 43
SoC_VOUT0_DATA20: RA1.7 U12.T22(GPMC0_AD12) ; also on sheet 43
SoC_VOUT0_DATA21: RA2.8 U12.T24(GPMC0_AD13) ; also on sheet 43
SoC_VOUT0_DATA22: RA1.5 U12.U25(GPMC0_AD14) ; also on sheet 43
SoC_VOUT0_DATA23: RA1.6 U12.U24(GPMC0_AD15) ; also on sheet 43
VSEL_SD_SOC: U12.P25(GPMC0_CLK) ; also on sheet 15
WKUP_I2C0_SCL: R73.2 R743.2 ; also on sheet 27
WKUP_I2C0_SCL_RC: C534.1 R74.2 R743.1
WKUP_I2C0_SDA: R71.2 R744.2 ; also on sheet 27
WKUP_I2C0_SDA_RC: C535.1 R744.1 U12.A9(WKUP_I2C0_SDA)
WKUP_LFOSCO_XI: C75.1 R764.1 U12.C2(WKUP_LFOSC0_XI) Y1.1
WKUP_LFOSCO_XO: C79.1 U12.C1(WKUP_LFOSC0_XO) Y1.2
WKUP_UART0_CTS_3V3: U12.C6(WKUP_UART0_CTSN) ; also on sheet 33
WKUP_UART0_RTS_3V3: U12.A4(WKUP_UART0_RTSN) ; also on sheet 33
WKUP_UART0_RX_3V3: U12.B4(WKUP_UART0_RXD) ; also on sheet 33
WKUP_UART0_TX_3V3: U12.C5(WKUP_UART0_TXD) ; also on sheet 33
N16931396: R15.2 U4.B2(CL)
N16931420: R13.1 U4.C1(OC)
N17395932: R74.1 U12.B9(WKUP_I2C0_SCL)
N19066697: R56.2 U12.M24(GPMC0_BE0N_CLE)
N19066711: R331.2 U12.U23(GPMC0_WAIT0)
N19066744: R55.2 U12.L25(GPMC0_WEN)
N20055845: R654.2 U12.L23(GPMC0_ADVN_ALE)
N20190775: R32.2 U12.D20(MCASP0_AFSX)
N20275668: R661.2 U100.1(A0)
N20275680: R663.1 U100.2(A1)
N20275684: R662.2 U100.11(~{INT})
N20275795: R664.2 U100.4(~{INT0})
N20275817: R665.2 U100.8(~{INT1})
N21984527: J25.2 R716.2
N22668832: TP124.1(TP) U12.B7(PMIC_LPM_EN0)
N22761976: J26.2 R718.2

Not connected (* = marked no-connect by the designer): J10 7* 9* 10* 11* 12*

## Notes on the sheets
sheet 34
- D-Note:
  WKUP_I2C0
  A pull-up is recommended for open-drain
  output type I2C interfaces, irrespective
  of the IO usage or IO configuration.
  Refer to the Pin Connectivity Requirements
  table of the SoC datasheet.
- SOC WKUP DOMAIN
- D-Note:
  Open-drain output type buffer I2C interfaces have slew rate
  requirement specified when pulled to 3.3 V. An RC is used
  to limit the slew rate
- V.
- D-Note:
  WKUP_CLKOUT0 is a buffered output of
  the high frequency oscillator (HFOSC0, 25MHz)
  available after reset as default output.
- D-Note:
  The only LFOSC0 register bits that should be changed by the customer are BP_C, PD_C, and
  CTRLMMR_WKUP_LFXOSC_TRIM[18:16], where PD_C is reset (0) to enable the oscillator and the BP_C
  bit is only set (1) to place the oscillator in bypass mode when using an LVCMOS clock source.
  The CTRLMMR_WKUP_LFXOSC_TRIM[18:16] bits are set based on the actual capacitance load applied to
  the crystal, as defined by the Load Capacitance Equation. The load capacitance range of the
  crystal will be half of the recommended capacitor value range, since they are connected in
  series with the resonant circuit of the crystal.
- ECS-.327-9-34QCS-TR
- C
- D-Note:
  WKUP_LFOSC0 has limited use case. Populate 0R to
  ground XI when LFOSC0 is not used. Refer to the SoC
  datasheet.
- SOC GPMC INTERFACE
- D-Note:
  Delete or reduce the series resistor value to 0R when buffers are not
  used. The series resistors can be used to isolate the alternative function
  for testing the bootmode configuration.
- D-Note:
  Addition of Series and Parallel resistors.
  Refer to the SoC data sheet for the recommended circuit
  configuration for pre-production boards and production
  boards.
- D-Note:
  Add a series resistor 0R when used as GPMC0_CLK.
- BOOTMODE PINS
- Signals from Bootmode buffer
- D-Note:
  Shorting of multiple boot mode inputs (IOs) together is not recommended or allowed
  since the IOs have alternative functions that could be configured after booting.
  Shorting the boot mode pins directly to VCC or ground is not recommended.
  Connect each of the boot mode pins through separate resistors. Choose the boot mode
  resistor value based on the use case (10K or similar).
- D-Note:
  LVCMOS IO buffers used to implement GPMC
  interface are off during reset and after reset until
  the host configures the interface. The recommendation
  is to add pulls for memory interface signals that can float.
  The required pulls for the GPMC interface signals are
  added on the GPMC interface add-on card.
- D-Note:
  When the boot mode isolation buffers are not
  used, connect the boot mode configuration
  resistors directly to the SoC boot mode input
  pins. Connect the SoC bootmode signal used for
  alternative function to the attached device
  through 0R for isolation or testing.
- D-Note:
  Connect SYS_BOOTMODE signals (output) from
  BOOTMODE configuration resistors and switches
  when bootmode buffers are not used
- R-Note:
  Series resistors are used to
  isolate the SoC BOOTMODE input
  control logic after the BOOTMODE
  inputs value is latched.
- D-Note:
  1. 1k resistor at the output of the buffer is recommended when the bootmode
  pins are used for alternate functions to limit the buffer current
  2. When bootmode isolation buffers are not used, connect the bootmode
  configuration resistors directly to the SoC bootmode input pins. Connect the
  SOC bootmode signal used for alternate function to the attached device
  through 0R for isolation or testing.
- PRU HEADER
- POWER SWITCH FOR PRU HEADER
- D-Note:
  Any SoC IO that has a trace connected but not being
  driven actively needs to be connected to an external
  pull. When adding pull is not feasible, ensure that the
  traces are routed away from noisy signals.
- D-Note:
  LDO can source up to
  500mA current
- Silk: PRU HDR
- D-Note:
  Processor IOs connected to the PRU Header are not fail-safe.
  No external input shall be driven when the starter kit is not
  powered-up.
sheet 35
- USER EXPANSION CONNECTOR
- D-Note:
  SoC IO buffers are off during reset. A parallel pull is recommended near
  to the attached device input that is being driven by the SoC IO (input does not float).
- R-Note:
  These supplies are off by default. The supplies are controlled
  by the below load switches and need to be enabled.
- D-Note:
  Processor IOs connected to USER EXPANSION CONNECTOR
  are not fail-safe. No external input shall be applied
  when the starter kit is not powered-up.
- C
- CAD Note:
  R32 (Series damping resistor) should be placed closer to the SoC.
- D-Note:
  EXP_CLKOUT0_SEL is
  high  by default to
  maintain compatibility
  with the the previous
  version EVM
- D-Note:
  Add-on boards are expected to take care of the
  connection polarity for  for the UART signals
  (cross-over of RX and TX or other signals).
- Silk: USER EXPN
- D-Note:
  U111 & U112 are added to provide support for connecting DANTE daughter card on the User
  Expansion Connector (without affecting the connection compatibility with the previous
  EVM version).
  For custom board designs, U111 & U112 can be deleted (based on the architecture).
- D-Note:
  AUDIO_EXT_REFCLK_EN is
  high  by default to maintain
  compatibility with the the
  previous version EVM
- I2C SWITCH FOR SoC_I2C2
- LOAD SWITCHES FOR USER EXPANSION CONNECTOR
- R-Note:
  All the I2C outputs are disabled by default.
- V
- I2C ADDRESS: 0x71
- V
- R-Note:
- The Starter Kit shall not be powered through the 5V0 or 3V3 supply pins on the 40-pin User Expansion Connector
  (the pins are output supply).
  User Expansion Connector I/O are not fail-safe and shall not be driven when AM62P Starter Kit is
  not powered.
  5V supply on User Expansion Connector can source 150mA max.
  3V3 supply on User Expansion Connector can source 500mA max.
- It should be connected to PORz of the SoC TBD
